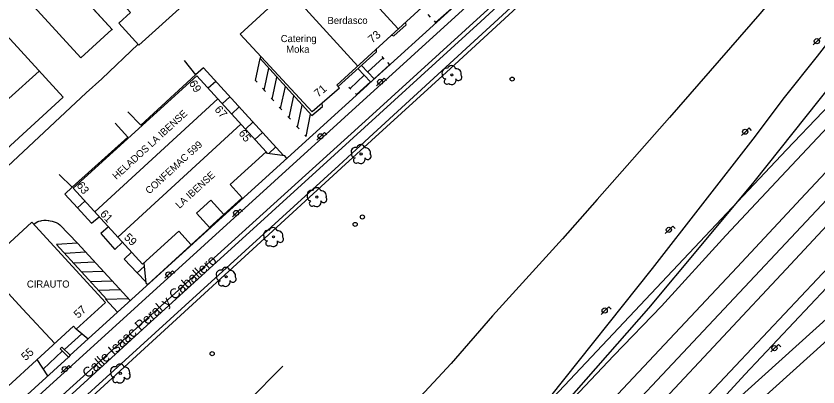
# Model space of a CAD drawing. Extents: x 282771 to 285132, y 4823109 to 4825496.
# Drawn here: x 282932.6 to 283130.2, y 4823249.3 to 4823340.8 of the extents above; entities that cross this region are included whole.
import ezdxf

# ---------------------------------------------------------------- set-up
doc = ezdxf.new("R2010")
doc.units = 0
for name, color, linetype in [('ACERA-BORDILLO', 7, 'Continuous'), ('ACERA-INTERIOR', 7, 'Continuous'), ('APARCAMIENTO', 7, 'Continuous'), ('ARBOL', 7, 'Continuous'), ('AUTOVIA', 7, 'Continuous'), ('CALLE-EJE', 7, 'Continuous'), ('CALLE-TEXTO', 7, 'Continuous'), ('EDIFICIO', 7, 'Continuous'), ('FAROLA', 7, 'Continuous'), ('MEDIANERA', 7, 'Continuous'), ('NUM-LOCAL', 7, 'Continuous'), ('POSTE', 7, 'Continuous'), ('SENAL-VIARIA', 7, 'Continuous'), ('TXT-EMPRESAS', 7, 'Continuous'), ('VALLA', 7, 'Continuous')]:
    doc.layers.add(name, color=color, linetype=linetype)

msp = doc.modelspace()

# ---------------------------------------------------------------- linework, layer by layer
at = {"layer": 'ACERA-BORDILLO'}
for points in [[(283046.24, 4823345.62), (282895.37, 4823208.28)], [(282891.09, 4823193.57), (283012.1, 4823303.96), (283016.4, 4823307.89), (283020.61, 4823311.74), (283055.41, 4823343.76)], [(283025.11, 4823336.12), (283025.7, 4823335.94), (283028.68, 4823338.65), (283028.56, 4823339.28)], [(283011.94, 4823323.44), (283021.44, 4823332.02), (283021.37, 4823332.69)], [(282992.82, 4823330.91), (282992.71, 4823330.38), (283005.47, 4823316.25), (283008.12, 4823318.53), (283008.02, 4823319.3)]]:
    msp.add_lwpolyline(points, dxfattribs=at)
at = {"layer": 'ACERA-INTERIOR'}
for points in [[(282950.32, 4823246.07), (283012.7, 4823303.29), (283012.8, 4823303.38), (283038.69, 4823327.01), (283056.09, 4823343.03), (283057.58, 4823344.48), (283058.87, 4823345.78), (283060.47, 4823347.5), (283062.19, 4823349.4), (283063.38, 4823350.73), (283065.07, 4823352.71), (283066.72, 4823354.86), (283067.46, 4823355.95), (283068.55, 4823357.57), (283069.33, 4823358.77), (283069.48, 4823359), (283071.02, 4823361.43), (283074.12, 4823366.59), (283079.95, 4823377.59), (283099.54, 4823415.81), (283100.08, 4823417.16), (283100.63, 4823419.98), (283100.92, 4823422.87)], [(283057.18, 4823360.1), (283057, 4823359.87), (283055.16, 4823357.68), (283053.83, 4823356.22), (283052.38, 4823354.69), (283050.9, 4823353.14), (283049.44, 4823351.59), (283047.94, 4823350.07), (283046.42, 4823348.59), (283044.84, 4823347.12), (283040.25, 4823342.94), (283039.78, 4823342.51), (283019.55, 4823324.09), (283019.07, 4823323.66), (282945.96, 4823257.11), (282945.48, 4823256.67), (282925.11, 4823238.13)], [(282943.43, 4823258.67), (282943.88, 4823259.14)]]:
    msp.add_lwpolyline(points, dxfattribs=at)
at = {"layer": 'APARCAMIENTO'}
for points in [[(283035.61, 4823339.63), (283035.97, 4823339.19), (283039.92, 4823342.7)], [(283034.75, 4823340.55), (283034.16, 4823341.21)], [(283023.26, 4823330.22), (283022.8, 4823330.82)], [(282973.99, 4823329.87), (282976.8, 4823326.28), (282963.36, 4823313.93), (282960.14, 4823317.2)], [(282991.98, 4823324.48), (282991.6, 4823324.91), (282992.71, 4823330.38)], [(283023.03, 4823330.52), (283019.26, 4823327.03)], [(283024.16, 4823329.34), (283024.58, 4823328.77), (283020.87, 4823325.36)], [(282998.48, 4823306.38), (282978.74, 4823328.07), (282976.8, 4823326.28)], [(282993.71, 4823322.56), (282994.85, 4823328)], [(283016.84, 4823327.86), (283019.96, 4823324.56)], [(283017.71, 4823328.64), (283020.87, 4823325.36)], [(282995.71, 4823320.32), (282996.89, 4823325.74)], [(283014.91, 4823322.97), (283018.39, 4823326.21)], [(282981.8, 4823324.7), (282979.89, 4823323.01)], [(282994.05, 4823322.23), (282993.29, 4823323)], [(282997.77, 4823318), (282999.01, 4823323.4)], [(283015.11, 4823322.79), (283014.63, 4823323.22)], [(283016.22, 4823321.75), (283016.49, 4823321.45), (283019.96, 4823324.56)], [(282985.27, 4823320.89), (282983.37, 4823319.19)], [(282999.87, 4823315.75), (283001.04, 4823321.14)], [(282996.15, 4823319.9), (282995.44, 4823320.58)], [(283001.98, 4823313.37), (283003.11, 4823318.85)], [(282987.53, 4823318.4), (282985.69, 4823316.64)], [(282998.1, 4823317.67), (282997.46, 4823318.31)], [(283000.24, 4823315.38), (282999.59, 4823316.05)], [(283003.79, 4823311.45), (283004.11, 4823311.14), (283005.13, 4823316.62)], [(282957.03, 4823314.36), (282960.17, 4823310.94), (282946.44, 4823298.58)], [(282990.94, 4823314.66), (282989.09, 4823312.91)], [(283002.38, 4823313), (283001.7, 4823313.66)], [(282993.3, 4823312.06), (282991.42, 4823310.35)], [(282999.34, 4823305.7), (282998.8, 4823306.34), (282994.53, 4823306.9), (282994.19, 4823307.32)], [(282996.47, 4823308.38), (282994.97, 4823306.99)], [(282943.24, 4823301.75), (282946.44, 4823298.58), (282944.57, 4823296.87), (282947.7, 4823293.48), (282951.22, 4823289.7), (282953.04, 4823291.31)], [(282947.7, 4823293.48), (282949.55, 4823295.13)], [(282937.03, 4823289.54), (282937.93, 4823290.14), (282938.18, 4823290.21), (282938.69, 4823290.32), (282938.94, 4823290.37), (282939.46, 4823290.42), (282939.72, 4823290.43), (282939.98, 4823290.43), (282940.49, 4823290.39), (282940.64, 4823290.36), (282941.01, 4823290.32), (282941.52, 4823290.2), (282942.01, 4823290.04), (282942.49, 4823289.84), (282942.95, 4823289.6), (282943.4, 4823289.33), (282947.73, 4823284.76)], [(282955.33, 4823288.79), (282953.49, 4823287.17), (282956.9, 4823283.23), (282958.79, 4823285)], [(282960.77, 4823270.59), (282947.73, 4823284.76), (282942.58, 4823284.48), (282954.9, 4823270.93)], [(282964.1, 4823279.87), (282964.6, 4823275.02), (282965.08, 4823274.62), (282975.75, 4823284.39)], [(282949.78, 4823282.52), (282944.58, 4823282.27)], [(282961.04, 4823282.53), (282959.25, 4823280.84), (282962.47, 4823277.45), (282964.57, 4823275.25)], [(282952.04, 4823280.07), (282946.8, 4823279.83)], [(282954.12, 4823277.8), (282948.83, 4823277.6)], [(282962.47, 4823277.45), (282964.18, 4823279.02)], [(282956.32, 4823275.41), (282950.93, 4823275.28)], [(282958.3, 4823273.27), (282952.94, 4823273.07)], [(282954.67, 4823270.93), (282960.28, 4823271.12)], [(282957.62, 4823267.72), (282954.67, 4823270.93)], [(282950.36, 4823261.09), (282947.43, 4823263.6)], [(282948.83, 4823262.39), (282944.49, 4823258.53)], [(282943.99, 4823258.12), (282939.28, 4823253.7)], [(282945.48, 4823256.67), (282943.43, 4823258.67)], [(282943.88, 4823259.14), (282945.96, 4823257.11)], [(282940.38, 4823252.02), (282937.77, 4823256.06)]]:
    msp.add_lwpolyline(points, dxfattribs=at)
at = {"layer": 'ARBOL'}
for centre in [(283039.97, 4823326.29), (283017.6, 4823306.79), (283006.72, 4823296.17), (282996.01, 4823286.33), (282984.34, 4823276.5), (282958.28, 4823252.66)]:
    msp.add_circle(centre, 0.255, dxfattribs=at)
for centre, radius, start, end in [((283038.64, 4823326.82), 1.1, 75.4318, 200.5561), ((283039.9, 4823327.55), 1.04, 15.6423, 161.3843), ((283041.03, 4823326.55), 1.27, 345.0327, 95.7993), ((283038.53, 4823326.25), 0.935, 168.599, 268.1324), ((283038.77, 4823324.7), 0.672, 113.7367, 309.4725), ((283039.91, 4823325), 1.09, 228.9545, 17.928), ((283041.64, 4823325.72), 0.797, 208.9625, 38.991), ((283017.53, 4823308.05), 1.04, 15.6423, 161.3843), ((283016.27, 4823307.32), 1.1, 75.4318, 200.5561), ((283018.66, 4823307.05), 1.27, 345.0327, 95.7993), ((283016.16, 4823306.75), 0.935, 168.599, 268.1324), ((283016.4, 4823305.2), 0.672, 113.7367, 309.4725), ((283017.54, 4823305.5), 1.09, 228.9545, 17.928), ((283019.27, 4823306.22), 0.797, 208.9625, 38.991), ((283005.39, 4823296.7), 1.1, 75.4318, 200.5561), ((283006.65, 4823297.43), 1.04, 15.6423, 161.3843), ((283007.78, 4823296.43), 1.27, 345.0327, 95.7993), ((283005.28, 4823296.13), 0.935, 168.599, 268.1324), ((283005.52, 4823294.58), 0.672, 113.7367, 309.4725), ((283006.66, 4823294.88), 1.09, 228.9545, 17.928), ((283008.39, 4823295.6), 0.797, 208.9625, 38.991), ((282994.68, 4823286.86), 1.1, 75.4318, 200.5561), ((282995.94, 4823287.59), 1.04, 15.6423, 161.3843), ((282997.07, 4823286.59), 1.27, 345.0327, 95.7993), ((282994.57, 4823286.29), 0.935, 168.599, 268.1324), ((282994.81, 4823284.75), 0.672, 113.7367, 309.4725), ((282995.95, 4823285.05), 1.09, 228.9545, 17.928), ((282997.68, 4823285.77), 0.797, 208.9625, 38.991), ((282983.01, 4823277.03), 1.1, 75.4318, 200.5561), ((282984.27, 4823277.76), 1.04, 15.6423, 161.3843), ((282985.4, 4823276.76), 1.27, 345.0327, 95.7993), ((282982.9, 4823276.46), 0.935, 168.599, 268.1324), ((282983.14, 4823274.91), 0.672, 113.7367, 309.4725), ((282984.28, 4823275.21), 1.09, 228.9545, 17.928), ((282986.01, 4823275.93), 0.797, 208.9625, 38.991), ((282956.95, 4823253.19), 1.1, 75.4318, 200.5561), ((282958.21, 4823253.92), 1.04, 15.6423, 161.3843), ((282959.34, 4823252.92), 1.27, 345.0327, 95.7993), ((282956.84, 4823252.62), 0.935, 168.599, 268.1324), ((282957.08, 4823251.07), 0.672, 113.7367, 309.4725), ((282958.22, 4823251.37), 1.09, 228.9545, 17.928), ((282959.95, 4823252.09), 0.797, 208.9625, 38.991)]:
    msp.add_arc(centre, radius, start, end, dxfattribs=at)
at = {"layer": 'AUTOVIA'}
for points in [[(282937.6, 4823109), (282977.48, 4823152.35), (283012.93, 4823191.4), (283122.43, 4823307.8), (283140.37, 4823326.59), (283156.3, 4823343.68), (283174.37, 4823363.05), (283189.4, 4823379.03), (283213.98, 4823405.38), (283235.1, 4823427.88), (283251.51, 4823445.34), (283273.63, 4823469.21)], [(282978.36, 4823109), (282982.29, 4823113.22), (283015.33, 4823148.06), (283030.62, 4823163.13), (283112.15, 4823252.38), (283144.35, 4823286.61), (283150.93, 4823293.65), (283163.66, 4823307.27), (283188.46, 4823333.08), (283260.48, 4823410.93), (283293.57, 4823446.2)]]:
    msp.add_lwpolyline(points, dxfattribs=at)
at = {"layer": 'CALLE-EJE'}
for points in [[(282957.42, 4823109), (283132.37, 4823295.56), (283199.66, 4823367.65), (283251.8, 4823422.83), (283294.29, 4823468.81)], [(283100.42, 4823427.84), (283073.07, 4823374.64), (283068.23, 4823365.51), (283061.78, 4823356.54), (283048.82, 4823342.46), (283019.53, 4823315.71), (282891.09, 4823199.33), (282803.87, 4823118.38)]]:
    msp.add_lwpolyline(points, dxfattribs=at)
at = {"layer": 'EDIFICIO'}
msp.add_line((282963.76, 4823279.56), (282972.73, 4823287.71), dxfattribs=at)
for points in [[(282999.65, 4823347.32), (283001.35, 4823345.47), (283032.83, 4823374.4), (283064.31, 4823403.33), (283064.73, 4823402.86), (283068.07, 4823405.85), (283074.14, 4823399.06), (283072.62, 4823395.65), (283071.91, 4823394.96), (283072.21, 4823394.7), (283062.16, 4823385.28), (283065.47, 4823381.74), (283057.94, 4823374.71), (283059.89, 4823372.59), (283052.27, 4823365.47), (283054.51, 4823363.06), (283011.64, 4823323.78), (283012.32, 4823323.03), (283005.55, 4823317.15), (282987.79, 4823336.37), (282999.65, 4823347.32)], [(282985.15, 4823353.84), (282980.04, 4823359.45), (282978.44, 4823357.99), (282951.98, 4823386.98), (282940.16, 4823376.19), (282935.13, 4823381.68), (282929.25, 4823376.4), (282960.81, 4823341.73), (282957.9, 4823339.08), (282962.88, 4823333.6), (282985.15, 4823353.84)], [(282956.38, 4823337.43), (282929.45, 4823366.8), (282921.79, 4823359.8), (282948.55, 4823330.48), (282956.21, 4823337.48)], [(282929.26, 4823307.1), (282894.91, 4823345.04), (282900.36, 4823349.97), (282905.14, 4823344.75), (282914.53, 4823353.32), (282944.18, 4823320.84), (282929.26, 4823307.1)], [(282977.1, 4823326.08), (282946.65, 4823298.33), (282963.76, 4823279.56)], [(282972.73, 4823287.71), (282975.75, 4823284.39), (282980.33, 4823288.55), (282977.02, 4823292.2), (282980.57, 4823295.43), (282983.81, 4823291.87), (282988.34, 4823295.98), (282985.35, 4823299.27), (282994.19, 4823307.32), (282977.1, 4823326.08)], [(282926.22, 4823277.18), (282924.54, 4823279.01), (282936.46, 4823289.96), (282954.65, 4823270.16), (282947.43, 4823263.6), (282946.78, 4823264.31), (282921.44, 4823241.11), (282912.61, 4823233.03), (282903.53, 4823224.72), (282895.64, 4823233.33), (282887.75, 4823241.95), (282891.09, 4823245.03), (282926.22, 4823277.18)]]:
    msp.add_lwpolyline(points, dxfattribs=at)
at = {"layer": 'FAROLA'}
for p, q in [((283129.97, 4823334.62), (283129.04, 4823333.68)), ((283130.91, 4823335.55), (283129.97, 4823334.62)), ((283023.3, 4823325.5), (283022.36, 4823324.57)), ((283023.89, 4823324.91), (283023.3, 4823325.5)), ((283022.36, 4823324.57), (283021.43, 4823323.63)), ((283113.25, 4823313.21), (283112.31, 4823312.28)), ((283113.84, 4823312.62), (283113.25, 4823313.21)), ((283007.67, 4823311.16), (283006.74, 4823310.22)), ((283008.61, 4823312.09), (283007.67, 4823311.16)), ((283009.2, 4823311.5), (283008.61, 4823312.09)), ((283112.31, 4823312.28), (283111.38, 4823311.34)), ((282987.82, 4823293.17), (282986.88, 4823292.24)), ((282988.41, 4823292.58), (282987.82, 4823293.17)), ((282986.88, 4823292.24), (282985.95, 4823291.3)), ((283093.49, 4823288.07), (283092.56, 4823287.13)), ((283094.43, 4823289), (283093.49, 4823288.07)), ((283095.02, 4823288.41), (283094.43, 4823289)), ((282971.11, 4823277.99), (282970.17, 4823277.06)), ((282971.7, 4823277.4), (282971.11, 4823277.99)), ((282970.17, 4823277.06), (282969.24, 4823276.12)), ((283077.68, 4823268.16), (283076.75, 4823267.22)), ((283078.62, 4823269.09), (283077.68, 4823268.16)), ((283079.21, 4823268.5), (283078.62, 4823269.09)), ((283120.45, 4823259.81), (283119.51, 4823258.88)), ((283121.04, 4823259.22), (283120.45, 4823259.81)), ((283119.51, 4823258.88), (283118.58, 4823257.94)), ((282944.66, 4823253.7), (282943.73, 4823252.76)), ((282945.6, 4823254.63), (282944.66, 4823253.7)), ((282946.19, 4823254.04), (282945.6, 4823254.63))]:
    msp.add_line(p, q, dxfattribs=at)
for centre in [(283129.93, 4823334.62), (283022.32, 4823324.57), (283112.27, 4823312.28), (283007.63, 4823311.16), (282986.84, 4823292.24), (283093.45, 4823288.07), (282970.13, 4823277.06), (283077.64, 4823268.16), (283119.47, 4823258.88), (282944.62, 4823253.7)]:
    msp.add_circle(centre, 0.637, dxfattribs=at)
at = {"layer": 'MEDIANERA'}
for points in [[(282956.38, 4823337.43), (282932.78, 4823363.24)], [(283026.78, 4823337.64), (283011.33, 4823354.64)], [(283016.77, 4823328.47), (283001.35, 4823345.47)], [(282938.32, 4823327.26), (282923.29, 4823313.7)], [(282951.97, 4823292.5), (282982.31, 4823320.37)], [(282957.66, 4823286.25), (282988, 4823314.12)], [(282942.12, 4823260.04), (282934.17, 4823268.61), (282926.22, 4823277.18)]]:
    msp.add_lwpolyline(points, dxfattribs=at)
at = {"layer": 'POSTE'}
for centre in [(283054.84, 4823325.26), (283017.93, 4823291.24), (283016.16, 4823289.42), (282980.92, 4823257.52)]:
    msp.add_circle(centre, 0.5, dxfattribs=at)
at = {"layer": 'SENAL-VIARIA'}
for points in [[(283276.05, 4823466.96), (283253.93, 4823443.09), (283237.5, 4823425.62), (283216.39, 4823403.13), (283191.81, 4823376.78), (283176.78, 4823360.8), (283158.71, 4823341.43), (283142.78, 4823324.34), (283122.43, 4823302.61), (283116.19, 4823295.93), (283107.51, 4823286.66), (283091.61, 4823269.21), (283079.89, 4823257.1), (283065.7, 4823242.04)], [(283280.88, 4823461.43), (283262.36, 4823441.37), (283248.46, 4823426.56), (283234.16, 4823411.6), (283221.64, 4823397.98), (283207.7, 4823383.11), (283194.34, 4823368.58), (283185.73, 4823359.47), (283174.68, 4823347.62), (283161.72, 4823333.96), (283148.1, 4823319.32), (283126.01, 4823295.73), (283110.25, 4823278.89), (283051.51, 4823216.17), (283012.64, 4823174.83), (282976, 4823135.59), (282951.13, 4823109)], [(283286.86, 4823454.29), (283272.47, 4823438.89), (283235.53, 4823399.38), (283215.12, 4823377.44), (283193.59, 4823354.41), (283172.93, 4823332.39), (283156.42, 4823314.75), (283139.11, 4823296.36), (283122.38, 4823278.33), (283091.31, 4823245.13), (283066.05, 4823218.28), (283047.86, 4823198.64), (283025.74, 4823175.04), (282975.19, 4823121.14), (282963.82, 4823109)], [(283057.2, 4823198.3), (283063.05, 4823204.98), (283075.48, 4823217.94), (283109.89, 4823254.51), (283142.09, 4823288.73), (283148.67, 4823295.77), (283161.41, 4823309.4), (283186.23, 4823335.24), (283192.35, 4823341.5), (283197.13, 4823345.85), (283204.61, 4823352.68), (283210.93, 4823358.38), (283217.22, 4823363.51), (283223.78, 4823368.93), (283232.99, 4823376.74), (283240.23, 4823382.68), (283255.84, 4823395.22), (283263.06, 4823401.26), (283277.81, 4823415.17), (283288.3, 4823425.97), (283300.17, 4823438.63)], [(282912.46, 4823216.64), (282963.84, 4823263.58), (283011.1, 4823306.6), (283047.14, 4823339.46), (283052.22, 4823344.17)], [(282941.22, 4823109), (282972.08, 4823142.26), (283014.9, 4823189.63), (283030.31, 4823206.94), (283050.76, 4823230.52), (283064.06, 4823246.63), (283089.45, 4823278.57), (283114.21, 4823310.43), (283121.96, 4823320.69), (283130.05, 4823330.96), (283134.14, 4823336.14)], [(283065.7, 4823242.04), (283065.66, 4823242), (283065.34, 4823242.31), (283088.52, 4823268.77), (283101.43, 4823284.22), (283114.45, 4823299.94), (283133.68, 4823324.07)], [(282983.81, 4823291.87), (282980.24, 4823288.64)], [(283147.33, 4823279.71), (283112.18, 4823247.93), (283079.11, 4823217.88), (283066.03, 4823206.2), (283057.2, 4823198.3)], [(283150.01, 4823276.75), (283114.87, 4823244.97), (283081.79, 4823214.91), (283059.5, 4823194.88), (283027.85, 4823164.55), (283012.69, 4823149.64), (282980.41, 4823116.25), (282973.62, 4823109)]]:
    msp.add_lwpolyline(points, dxfattribs=at)
at = {"layer": 'VALLA'}
for points in [[(283221.51, 4823457.94), (283209.47, 4823445.57), (283202.88, 4823438.45), (283192.24, 4823428.02), (283184.69, 4823420.89), (283161.86, 4823395.07), (283142.33, 4823372.61), (283115.86, 4823341.35), (283093.64, 4823315.78), (283075.8, 4823295.56), (283067.25, 4823285.86), (283050.03, 4823266.87), (283039.78, 4823255.11), (283027.78, 4823242.18), (283012.18, 4823219.55), (282993.88, 4823193.07), (282982.26, 4823178.64), (282969.03, 4823162.72), (282953.11, 4823143.51), (282944.25, 4823133.39), (282930.86, 4823121.71), (282917.59, 4823109.07), (282917.53, 4823109)], [(282962.65, 4823333.88), (282953.74, 4823325.36), (282949.85, 4823321.91), (282918.84, 4823292.87), (282907.61, 4823282.89)], [(282998.32, 4823254.43), (282989.71, 4823245.7), (282981.35, 4823239.21), (282956.16, 4823216.58), (282929.57, 4823192.83), (282911.56, 4823181.66), (282907.37, 4823177.87), (282891.09, 4823163.14), (282850.08, 4823126.05)]]:
    msp.add_lwpolyline(points, dxfattribs=at)

# ---------------------------------------------------------------- texts
at = {"layer": 'CALLE-TEXTO'}
msp.add_text('Calle Isaac Peral y Caballero', height=2.5, rotation=42.1781, dxfattribs=at).set_placement((282950.29, 4823251.29))
at = {"layer": 'NUM-LOCAL'}
for s, rotation, p in [('73', 40.1009, (283020.36, 4823334)), ('69', 302.1958, (282975.13, 4823324.25)), ('71', 40.1009, (283007.06, 4823320.66)), ('67', 310.7636, (282981.37, 4823317.68)), ('65', 307.8984, (282987.31, 4823311.88)), ('63', 306.8202, (282947.39, 4823299.04)), ('61', 313.6497, (282953.14, 4823291.86)), ('59', 316.4163, (282959.05, 4823285.99)), ('57', 42.3477, (282947.89, 4823266.1)), ('55', 42.3477, (282934.95, 4823255.66))]:
    msp.add_text(s, height=2, rotation=rotation, dxfattribs=at).set_placement(p)
at = {"layer": 'TXT-EMPRESAS'}
for s, p in [('Berdasco', (283009.33, 4823338.87)), ('Catering', (282997.81, 4823334.39)), ('Moka', (282999.16, 4823331.76)), ('CIRAUTO', (282935.26, 4823273.82))]:
    msp.add_text(s, height=1.75, dxfattribs=at).set_placement(p)
for s, p in [('HELADOS LA IBENSE', (282957.31, 4823300.35)), ('CONFEMAC 599', (282965.43, 4823296.76)), ('LA IBENSE', (282972.87, 4823293.2))]:
    msp.add_text(s, height=1.75, rotation=42.5343, dxfattribs=at).set_placement(p)

doc.saveas('drawing.dxf')
